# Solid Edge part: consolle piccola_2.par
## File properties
Last saved by: i.fialdini
Revision: 62
Tipo di contenuto documento: 0
Accuracy: 0.990
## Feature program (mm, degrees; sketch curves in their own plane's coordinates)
body "unnamed Body 1"
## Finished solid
Body 1: solid body, 4 faces, 4 edges, 0 vertices.
  Faces by surface: cylinder 2, plane 2
  Edges by curve: circle 4
Bounding box of the edges (mm): 18.950 x 18.950 x 53.817, from (194.0767, -554.5802, 648.6083) to (213.0264, -535.6304, 702.4253).
Cylindrical faces by radius (mm): R7 x1, R8.5 x1
Planar faces by outward normal: oblique 2
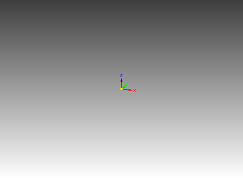
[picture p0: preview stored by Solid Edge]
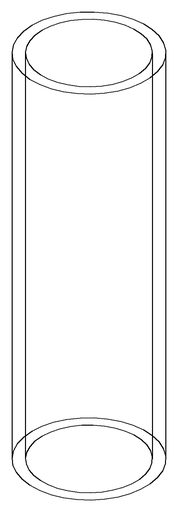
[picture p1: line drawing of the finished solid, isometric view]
